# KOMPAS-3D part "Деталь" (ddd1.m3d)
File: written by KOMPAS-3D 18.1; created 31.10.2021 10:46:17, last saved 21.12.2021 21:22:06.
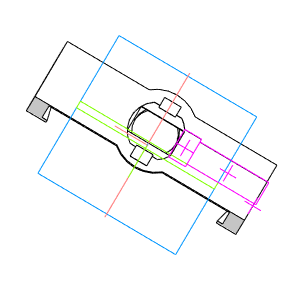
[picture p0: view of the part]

Document properties: Автор: 111; Полное имя файла: C:\Users\admin\Desktop\ffb\ddd1.m3d

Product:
- Part/product: Деталь
    Материал: Пенопласт ПЭ-2  ТУ В-172-70 (density 270 kg/m3)
    Масса: 0.00798896

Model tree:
1. Эскиз:1
2. Элемент выдавливания:1
     Расстояние 1 = 110
3. Эскиз:5  (with: Элемент выдавливания:1)
4. Элемент выдавливания:4
     Расстояние 2 = 103
5. Эскиз:8  (with: Элемент выдавливания:1)
6. Элемент выдавливания:7
     Расстояние 1 = -21
7. Эскиз:10  (with: Элемент выдавливания:1, Элемент выдавливания:4)
8. Элемент выдавливания:8
     Расстояние 1 = -10
9. Эскиз:14  (with: Элемент выдавливания:8)
10. Элемент выдавливания:12
     Расстояние 1 = 100
11. Эскиз:16  (with: Элемент выдавливания:1, Элемент выдавливания:12)
12. Элемент выдавливания:14
     Расстояние 2 = 110
13. Эскиз:17  (with: Элемент выдавливания:1, Элемент выдавливания:12)
14. Элемент выдавливания:15
     Расстояние 2 = 110
15. Эскиз:19  (with: Элемент выдавливания:1)
16. Элемент выдавливания:19
     Расстояние 1 = -7
17. Эскиз:20  (with: Элемент выдавливания:4, Элемент выдавливания:7)
18. Элемент выдавливания:20
     Расстояние 2 = -103
19. Эскиз:21  (with: Элемент выдавливания:7)
20. Элемент выдавливания:21
     Расстояние 2 = 20
21. Эскиз:22  (with: Элемент выдавливания:4, Элемент выдавливания:19, Элемент выдавливания:20)
22. Элемент выдавливания:22
     Расстояние 2 = -88
23. Эскиз:23  (with: Элемент выдавливания:1, Элемент выдавливания:12, Элемент выдавливания:14)
24. Элемент выдавливания:23
     Расстояние 1 = -11
25. Эскиз:24  (with: Элемент выдавливания:1)
26. Элемент выдавливания:24
     Расстояние 2 = 1.6
27. Эскиз:25  (with: Элемент выдавливания:24)
28. Эскиз:27  (with: Элемент выдавливания:24)
29. Элемент выдавливания:25
     Расстояние 1 = -3.3
30. Эскиз:28  (with: Элемент выдавливания:24)
31. Элемент выдавливания:26
     Расстояние 1 = 1.6
32. Эскиз:29  (with: Элемент выдавливания:1, Элемент выдавливания:24)
33. Элемент выдавливания:27
     Расстояние 2 = 2
34. Эскиз:33  (with: Элемент выдавливания:1)
35. Элемент выдавливания:29
     Расстояние 1 = 1
36. Эскиз:34  (with: Элемент выдавливания:12)
37. Элемент выдавливания:30
     Расстояние 2 = 77
38. Эскиз:36  (with: Элемент выдавливания:24)
39. Элемент выдавливания:31
     Расстояние 2 = 4
40. Эскиз:37  (with: Элемент выдавливания:1)
41. Элемент выдавливания:32  (labels: Пенопласт ПЭ-2  ТУ В-172-70)
     Расстояние 2 = 10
